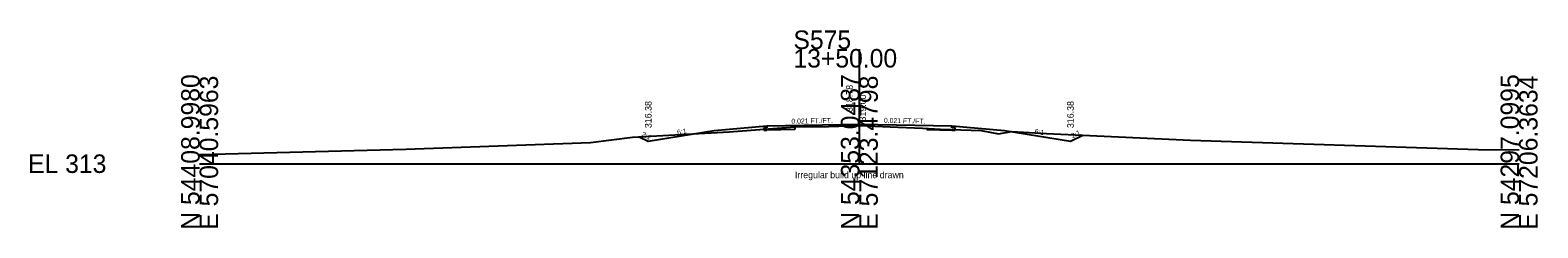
# Model space of a CAD drawing. Extents: x 10119 to 10347, y 94341 to 98867.
# Drawn here: x 10118.6 to 10347.2, y 97341.1 to 97371 of the extents above; entities that cross this region are included whole.
import ezdxf

# ---------------------------------------------------------------- set-up
doc = ezdxf.new("R2010")
doc.units = 0
for name, color, linetype in [('Level 10', 7, 'Continuous'), ('Level 11', 7, 'Continuous'), ('Level 12', 7, 'Continuous'), ('Level 32', 7, 'Continuous'), ('Level 33', 7, 'Continuous'), ('Level 50', 7, 'Continuous'), ('Level 59', 7, 'Continuous'), ('Level 6', 7, 'Continuous'), ('Level 60', 7, 'Continuous'), ('Level 63', 7, 'Continuous'), ('Level 7', 7, 'Continuous')]:
    doc.layers.add(name, color=color, linetype=linetype)

msp = doc.modelspace()

# ---------------------------------------------------------------- linework, layer by layer
at = {"layer": 'Level 11'}
for p, q in [((10230.31, 97356.23), (10229.81, 97356.22)), ((10229.81, 97356.22), (10229.81, 97355.88)), ((10229.81, 97355.88), (10230.31, 97355.89)), ((10230.31, 97356.52), (10230.31, 97356.23)), ((10258.31, 97356.23), (10258.31, 97356.52)), ((10258.81, 97356.22), (10258.31, 97356.23)), ((10258.31, 97355.89), (10258.81, 97355.88)), ((10258.81, 97355.88), (10258.81, 97356.22))]:
    msp.add_line(p, q, dxfattribs=at)
at = {"layer": 'Level 12'}
for p, q in [((10234.54, 97355.98), (10230.31, 97355.89)), ((10234.54, 97356.36), (10234.54, 97355.98)), ((10254.55, 97356.16), (10254.55, 97355.97)), ((10254.55, 97355.97), (10258.31, 97355.89))]:
    msp.add_line(p, q, dxfattribs=at)
at = {"layer": 'Level 59'}
for p, q in [((10230.31, 97356.52), (10244.31, 97356.81)), ((10244.31, 97356.81), (10258.31, 97356.52))]:
    msp.add_line(p, q, dxfattribs=at)
at = {"layer": 'Level 6'}
for p, q in [((10222.31, 97355.85), (10230.31, 97356.52)), ((10258.31, 97356.52), (10266.31, 97355.85))]:
    msp.add_line(p, q, dxfattribs=at)
at = {"layer": 'Level 60'}
for p, q in [((10209.9, 97354.82), (10224.56, 97355.61)), ((10224.56, 97355.61), (10234.52, 97356.36)), ((10234.52, 97356.36), (10239.62, 97356.44)), ((10239.62, 97356.44), (10244.32, 97356.59)), ((10244.32, 97356.59), (10248.97, 97356.39)), ((10248.97, 97356.39), (10253.87, 97356.2)), ((10253.87, 97356.2), (10256.62, 97356.03)), ((10256.62, 97356.03), (10262.78, 97355.82)), ((10262.78, 97355.82), (10265.4, 97355.3)), ((10265.4, 97355.3), (10267.43, 97355.67)), ((10267.43, 97355.67), (10272.69, 97355.38)), ((10272.69, 97355.38), (10294.52, 97354.36)), ((10144.31, 97352.21), (10175.57, 97352.98)), ((10175.57, 97352.98), (10203.58, 97354.02)), ((10203.58, 97354.02), (10209.9, 97354.82)), ((10294.52, 97354.36), (10338.1, 97352.97)), ((10338.1, 97352.97), (10344.31, 97352.89))]:
    msp.add_line(p, q, dxfattribs=at)
at = {"layer": 'Level 63'}
for p, q in [((10244.31, 97350.81), (10244.31, 97368.15)), ((10144.31, 97350.81), (10244.31, 97350.81)), ((10244.31, 97350.81), (10344.31, 97350.81))]:
    msp.add_line(p, q, dxfattribs=at)
at = {"layer": 'Level 7'}
for p, q in [((10212.31, 97354.19), (10222.31, 97355.85)), ((10266.31, 97355.85), (10276.31, 97354.19)), ((10210.94, 97354.88), (10212.31, 97354.19)), ((10276.31, 97354.19), (10278.18, 97355.12))]:
    msp.add_line(p, q, dxfattribs=at)

# ---------------------------------------------------------------- texts
at = {"layer": 'Level 10'}
msp.add_text('318.78', height=1, rotation=90, dxfattribs=at).set_placement((10243.31, 97358.63))
at = {"layer": 'Level 32'}
for s, rotation, p in [('0.021 FT./FT.', 1.1916, (10234.02, 97356.85)), ('0.021 FT./FT.', 358.8084, (10248.03, 97356.99)), ('2:1', 333.435, (10211.23, 97355.01)), ('6:1', 9.4623, (10216.75, 97355.18)), ('6:1', 350.5377, (10270.83, 97355.36)), ('2:1', 26.5651, (10276.63, 97354.63))]:
    msp.add_text(s, height=0.75, rotation=rotation, dxfattribs=at).set_placement(p)
at = {"layer": 'Level 33'}
for p in [(10212.81, 97356.19), (10276.81, 97356.19)]:
    msp.add_text('316.38', height=1, rotation=90, dxfattribs=at).set_placement(p)
at = {"layer": 'Level 50'}
msp.add_text('Irregular build up line drawn', height=1, dxfattribs=at).set_placement((10234.54, 97348.61))
at = {"layer": 'Level 59'}
msp.add_text(' 319.00', height=1, rotation=90, dxfattribs=at).set_placement((10245.31, 97356.81))
at = {"layer": 'Level 63'}
for s, p in [('S575', (10234.32, 97368.15)), ('13+50.00', (10234.32, 97365.35)), ('EL 313', (10118.31, 97349.41))]:
    msp.add_text(s, height=2.8, dxfattribs=at).set_placement(p)
for s, p in [('N 54408.9980', (10144.31, 97340.81)), ('E 57040.5963', (10147.11, 97340.81)), ('N 54353.0487', (10244.31, 97340.81)), ('E 57123.4798', (10247.11, 97340.81)), ('N 54297.0995', (10344.31, 97340.81)), ('E 57206.3634', (10347.11, 97340.81))]:
    msp.add_text(s, height=2.8, rotation=90, dxfattribs=at).set_placement(p)

doc.saveas('drawing.dxf')
